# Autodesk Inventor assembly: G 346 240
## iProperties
Company: Mayer & Müller AG Schaltgeräte
Created: 2005-10
Part Number: G 346 240
Document SubType Name: Assembly
Designer: I.Baliuc
Manufacturer: Standard
Standards Organization: Custom
Description: Isolator
Mass: 571.443 g
Surface Area: 681.023 cm^2
Volume: 392.991 cm^3
Density: 1.45409 g/cm^3
Author: T.Messerschmitt
Revision Number: 346240
